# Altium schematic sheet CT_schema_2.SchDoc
size 396 x 205 mm
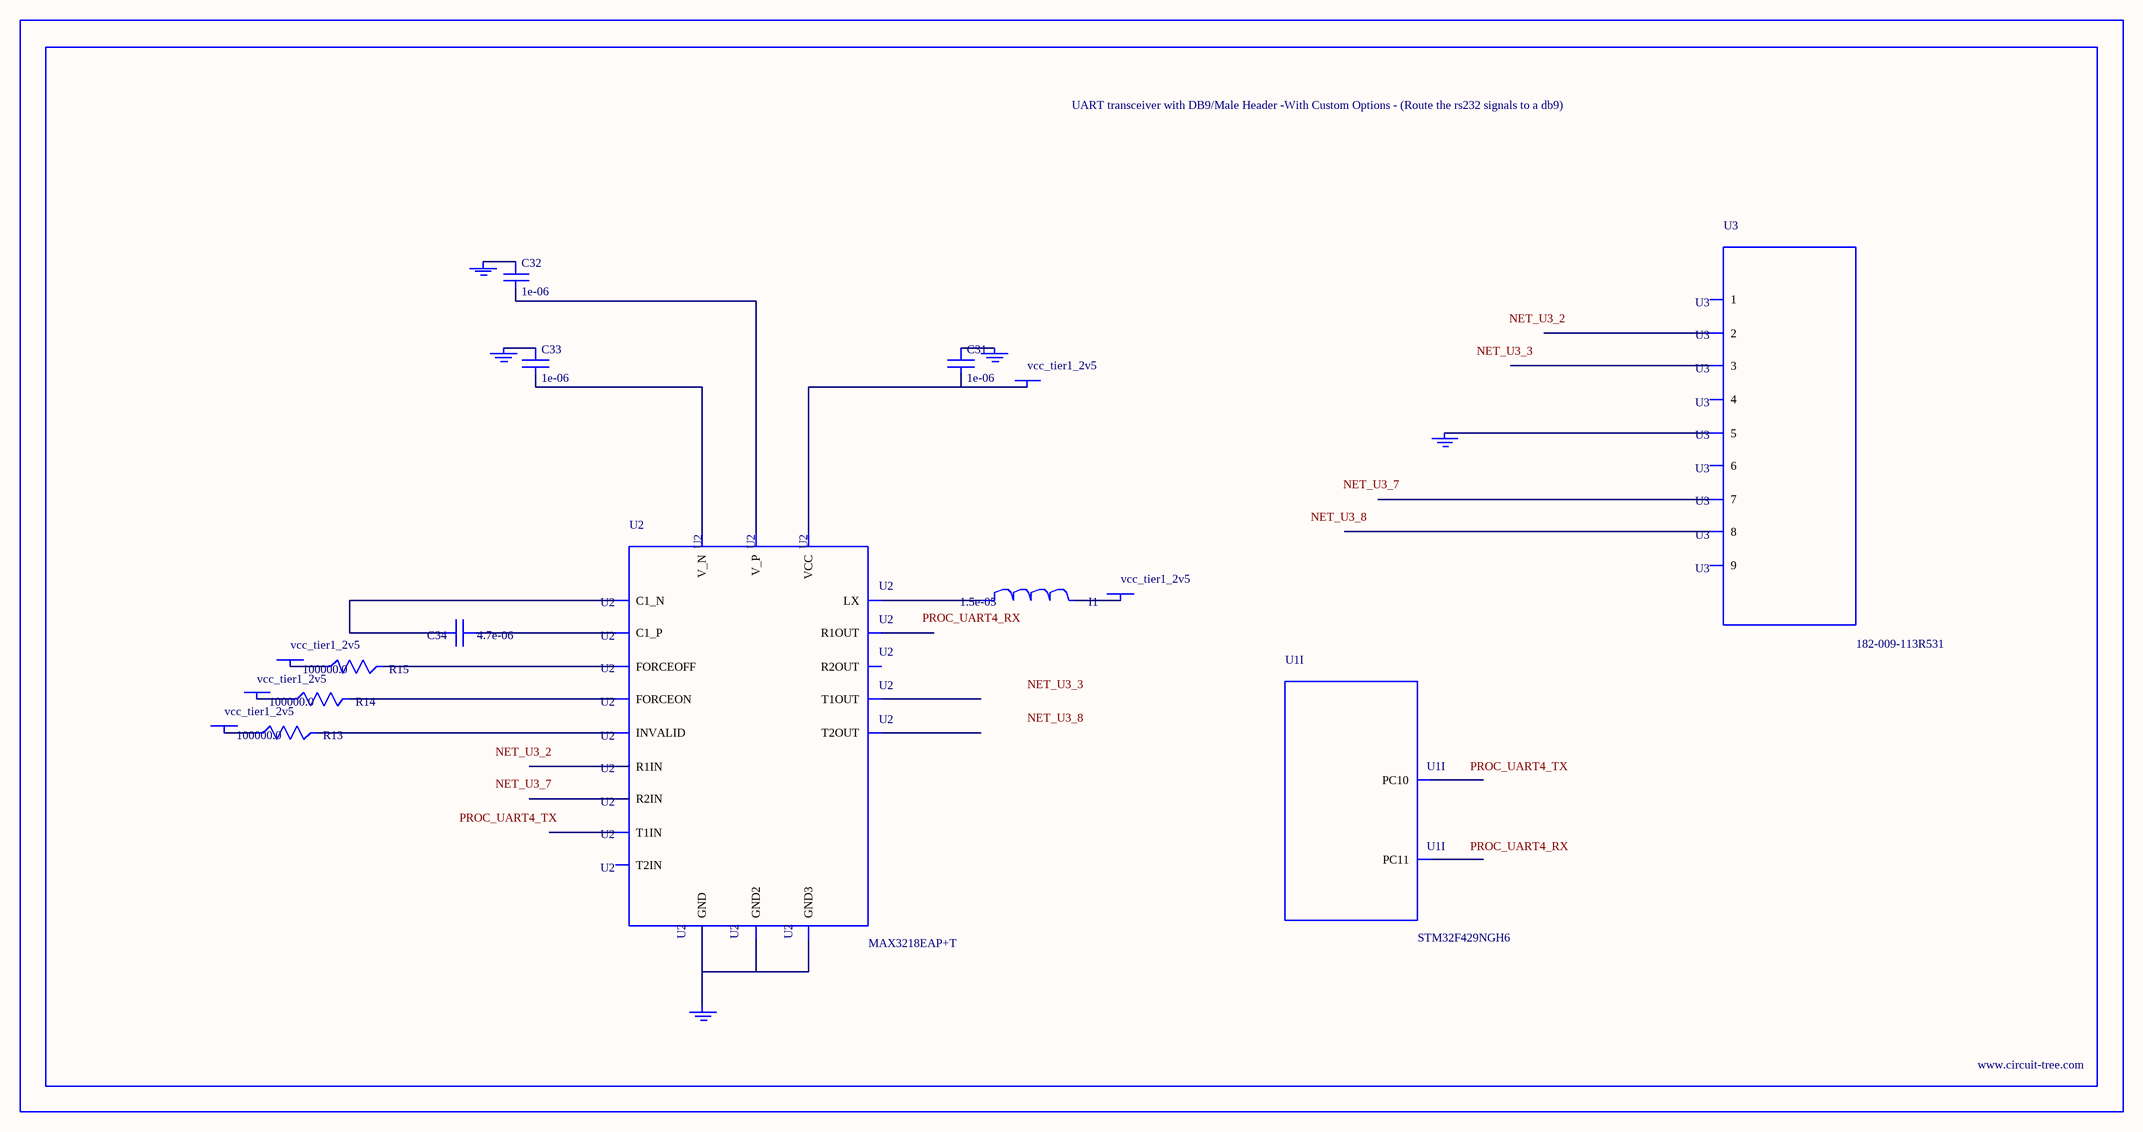
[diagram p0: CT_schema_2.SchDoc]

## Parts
BORDER1  (no value)
C31  1e-06  [C0603]
C32  1e-06  [C0603]
C33  1e-06  [C0603]
C34  4.7e-06  [C0805]
GND_INSTANCE_1_0  (no value)
GND_INSTANCE_1_1  (no value)
GND_INSTANCE_1_2  (no value)
GND_INSTANCE_1_3  (no value)
GND_INSTANCE_1_4  (no value)
I1  1.5e-05  [L1210]
POWER_INSTANCE_1_0  vcc_tier1_2v5
POWER_INSTANCE_1_1  vcc_tier1_2v5
POWER_INSTANCE_1_2  vcc_tier1_2v5
POWER_INSTANCE_1_3  vcc_tier1_2v5
POWER_INSTANCE_1_4  vcc_tier1_2v5
R13  100000.0  [R0603]
R14  100000.0  [R0603]
R15  100000.0  [R0603]
U1  STM32F429NGH6  [TFBGA216]  (part I of 16)
U2  MAX3218EAP+T  [SSOP-20]
U3  182-009-113R531  [182-009-MALE]

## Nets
NetC31_1: C31.1 GND_INSTANCE_1_0.0(GND)
NetC31_2: C31.2 POWER_INSTANCE_1_4.0(PWR) U2.6(VCC)
NetC32_1: C32.1 GND_INSTANCE_1_2.0(GND)
NetC32_2: C32.2 U2.19(V_P)
NetC33_1: C33.1 GND_INSTANCE_1_1.0(GND)
NetC33_2: C33.2 U2.15(V_N)
NetC34_1: C34.1 U2.18(C1_P)
NetC34_2: C34.2 U2.16(C1_N)
NetGND_INSTANCE_1_3_0: GND_INSTANCE_1_3.0(GND) U2.5(GND) U2.17(GND2) U2.20(GND3)
NetGND_INSTANCE_1_4_0: GND_INSTANCE_1_4.0(GND) U3.5
NetI1_1: I1.1 U2.1(LX)
NetI1_2: I1.2 POWER_INSTANCE_1_0.0(PWR)
NetPOWER_INSTANCE_1_1_0: POWER_INSTANCE_1_1.0(PWR) R13.1
NetPOWER_INSTANCE_1_2_0: POWER_INSTANCE_1_2.0(PWR) R14.1
NetPOWER_INSTANCE_1_3_0: POWER_INSTANCE_1_3.0(PWR) R15.1
NetR13_2: R13.2 U2.2(INVALID)
NetR14_2: R14.2 U2.3(FORCEON)
NetR15_2: R15.2 U2.4(FORCEOFF)

Not connected (* = marked no-connect by the designer): U1 B13(PC11) B14(PC10); U2 7(T1IN) 8(T2IN) 9(R1OUT) 10(R2OUT) 11(R2IN) 12(R1IN) 13(T2OUT) 14(T1OUT); U3 1 2 3 4 6 7 8 9

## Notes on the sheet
- Labels drawn without touching a wire or pin: NET_U3_2, NET_U3_3, NET_U3_7, NET_U3_8, PROC_UART4_RX, PROC_UART4_TX

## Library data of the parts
BORDER1 = BORDER_PAGE1
C31-C33 = C0603C105K3RACTU
C34 = C0805C475K4RACTU
GND_INSTANCE_1_0-GND_INSTANCE_1_4 = GND
I1 = L1210R150MDWIT
POWER_INSTANCE_1_0-POWER_INSTANCE_1_4 = PWR
R13-R15 = RC0603JR-07100KL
